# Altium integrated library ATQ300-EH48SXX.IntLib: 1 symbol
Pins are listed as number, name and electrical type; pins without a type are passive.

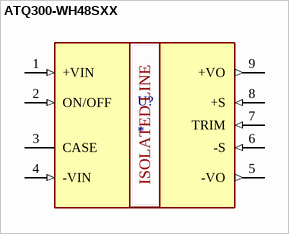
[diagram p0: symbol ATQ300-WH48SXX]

## ATQ300-WH48SXX
designator U?
300 W, 18-75VDC 4:1 Input Range, Single Regulated Output, 1/2 Brick, 1500 Vdc Isolation, Dc-Dc Converter; Power: 300W; Output: 12,15,24,28,48,51V; MF: ATAQ Inc.; MP: ATQ300-WH48SXX
footprint ATQ_HALF_BRICK
pins: 1 +VIN (in), 2 ON/OFF (in), 3 CASE, 4 -VIN (in), 5 -VO (out), 6 -S (in), 7 TRIM (in), 8 +S (in), 9 +VO (out)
